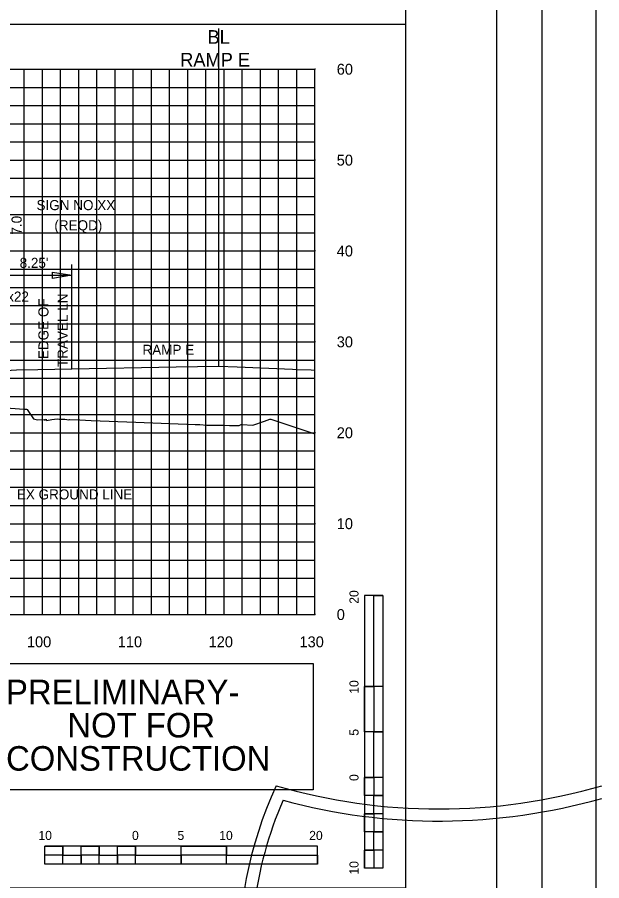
# Model space of a CAD drawing. Extents: x 1797809 to 2198143, y 249608 to 1237864.
# Drawn here: x 2195486 to 2195550.3, y 1237133.8 to 1237228.8 of the extents above; entities that cross this region are included whole.
import ezdxf

# ---------------------------------------------------------------- set-up
doc = ezdxf.new("R2010")
doc.units = 0
for name, color, linetype in [('10', 7, 'Continuous'), ('29', 7, 'Continuous'), ('3', 7, 'Continuous'), ('31', 7, 'Continuous'), ('60', 7, 'Continuous'), ('Default', 7, 'Continuous'), ('DESIGN - SHEET - Light Grid', 7, 'Continuous'), ('DESIGN - TRAFFIC CONTROL PERMANENT - Signs', 7, 'Continuous'), ('GSCOLORFILL', 7, 'Continuous'), ('GSDIMS', 7, 'Continuous'), ('GSOUTLINE', 7, 'Continuous'), ('GSSHT', 7, 'Continuous'), ('Level 30', 7, 'Continuous'), ('Level 45', 7, 'Continuous'), ('Level 55', 7, 'Continuous'), ('Level 61', 7, 'Continuous')]:
    doc.layers.add(name, color=color, linetype=linetype)

msp = doc.modelspace()

# ---------------------------------------------------------------- linework, layer by layer
at = {"layer": '29'}
for p, q in [((2195524.255, 1237165.195), (2195524.255, 1237135.195)), ((2195526.255, 1237165.195), (2195524.255, 1237165.195)), ((2195526.255, 1237165.195), (2195526.255, 1237155.195)), ((2195526.255, 1237165.195), (2195526.255, 1237135.195)), ((2195525.255, 1237155.195), (2195524.255, 1237155.195)), ((2195526.255, 1237155.195), (2195524.255, 1237155.195)), ((2195525.255, 1237155.195), (2195525.255, 1237150.195)), ((2195526.255, 1237150.195), (2195524.255, 1237150.195)), ((2195526.255, 1237150.195), (2195525.255, 1237150.195)), ((2195526.255, 1237150.195), (2195526.255, 1237145.195)), ((2195525.255, 1237145.195), (2195524.255, 1237145.195)), ((2195526.255, 1237145.195), (2195524.255, 1237145.195)), ((2195525.255, 1237145.195), (2195525.255, 1237143.195)), ((2195526.255, 1237143.195), (2195525.255, 1237143.195)), ((2195526.255, 1237143.195), (2195526.255, 1237141.195)), ((2195525.255, 1237141.195), (2195524.255, 1237141.195)), ((2195525.255, 1237141.195), (2195525.255, 1237139.195)), ((2195526.255, 1237139.195), (2195525.255, 1237139.195)), ((2195526.255, 1237139.195), (2195526.255, 1237137.195)), ((2195519.051, 1237137.63), (2195489.051, 1237137.63)), ((2195489.051, 1237135.63), (2195489.051, 1237137.63)), ((2195491.051, 1237136.63), (2195491.051, 1237137.63)), ((2195495.051, 1237136.63), (2195495.051, 1237137.63)), ((2195499.051, 1237136.63), (2195499.051, 1237137.63)), ((2195499.051, 1237135.63), (2195499.051, 1237137.63)), ((2195504.051, 1237135.63), (2195504.051, 1237137.63)), ((2195509.051, 1237136.63), (2195509.051, 1237137.63)), ((2195509.051, 1237135.63), (2195509.051, 1237137.63)), ((2195519.051, 1237135.63), (2195519.051, 1237137.63)), ((2195491.051, 1237136.63), (2195489.051, 1237136.63)), ((2195493.051, 1237135.63), (2195493.051, 1237136.63)), ((2195495.051, 1237136.63), (2195493.051, 1237136.63)), ((2195497.051, 1237135.63), (2195497.051, 1237136.63)), ((2195499.051, 1237136.63), (2195497.051, 1237136.63)), ((2195504.051, 1237135.63), (2195504.051, 1237136.63)), ((2195509.051, 1237136.63), (2195504.051, 1237136.63)), ((2195525.255, 1237137.195), (2195524.255, 1237137.195)), ((2195525.255, 1237137.195), (2195525.255, 1237135.195)), ((2195519.051, 1237135.63), (2195489.051, 1237135.63)), ((2195493.051, 1237135.63), (2195491.051, 1237135.63)), ((2195497.051, 1237135.63), (2195495.051, 1237135.63)), ((2195504.051, 1237135.63), (2195499.051, 1237135.63)), ((2195519.051, 1237135.63), (2195509.051, 1237135.63)), ((2195526.255, 1237135.195), (2195524.255, 1237135.195))]:
    msp.add_line(p, q, dxfattribs=at)
for points in [[(2195525.255, 1237155.195), (2195525.255, 1237165.195), (2195526.255, 1237165.195), (2195526.255, 1237155.195)], [(2195524.255, 1237150.195), (2195524.255, 1237155.195), (2195525.255, 1237155.195), (2195525.255, 1237150.195)], [(2195525.255, 1237145.195), (2195525.255, 1237150.195), (2195526.255, 1237150.195), (2195526.255, 1237145.195)], [(2195524.255, 1237143.195), (2195524.255, 1237145.195), (2195525.255, 1237145.195), (2195525.255, 1237143.195)], [(2195525.255, 1237141.195), (2195525.255, 1237143.195), (2195526.255, 1237143.195), (2195526.255, 1237141.195)], [(2195524.255, 1237139.195), (2195524.255, 1237141.195), (2195525.255, 1237141.195), (2195525.255, 1237139.195)], [(2195525.255, 1237137.195), (2195525.255, 1237139.195), (2195526.255, 1237139.195), (2195526.255, 1237137.195)], [(2195489.051, 1237137.63), (2195491.051, 1237137.63), (2195491.051, 1237136.63), (2195489.051, 1237136.63)], [(2195493.051, 1237137.63), (2195495.051, 1237137.63), (2195495.051, 1237136.63), (2195493.051, 1237136.63)], [(2195497.051, 1237137.63), (2195499.051, 1237137.63), (2195499.051, 1237136.63), (2195497.051, 1237136.63)], [(2195504.051, 1237137.63), (2195509.051, 1237137.63), (2195509.051, 1237136.63), (2195504.051, 1237136.63)], [(2195491.051, 1237136.63), (2195493.051, 1237136.63), (2195493.051, 1237135.63), (2195491.051, 1237135.63)], [(2195495.051, 1237136.63), (2195497.051, 1237136.63), (2195497.051, 1237135.63), (2195495.051, 1237135.63)], [(2195499.051, 1237136.63), (2195504.051, 1237136.63), (2195504.051, 1237135.63), (2195499.051, 1237135.63)], [(2195509.051, 1237136.63), (2195519.051, 1237136.63), (2195519.051, 1237135.63), (2195509.051, 1237135.63)], [(2195524.255, 1237135.195), (2195524.255, 1237137.195), (2195525.255, 1237137.195), (2195525.255, 1237135.195)]]:
    msp.add_lwpolyline(points, close=True, dxfattribs=at)
at = {"layer": '3'}
for p, q in [((2195228.783, 1237228.046), (2195528.783, 1237228.046)), ((2195492.021, 1237190.154), (2195492.021, 1237201.603))]:
    msp.add_line(p, q, dxfattribs=at)
at = {"layer": '60'}
for p, q in [((2195518.783, 1237163.106), (2195518.783, 1237223.106)), ((2195518.843, 1237223.106), (2195518.783, 1237223.106)), ((2195518.843, 1237213.106), (2195518.783, 1237213.106)), ((2195518.843, 1237203.106), (2195518.783, 1237203.106)), ((2195518.843, 1237193.106), (2195518.783, 1237193.106)), ((2195518.843, 1237183.106), (2195518.783, 1237183.106)), ((2195518.843, 1237173.106), (2195518.783, 1237173.106)), ((2195388.783, 1237163.106), (2195518.783, 1237163.106)), ((2195488.783, 1237163.046), (2195488.783, 1237163.106)), ((2195498.783, 1237163.046), (2195498.783, 1237163.106)), ((2195508.783, 1237163.046), (2195508.783, 1237163.106)), ((2195518.783, 1237163.046), (2195518.783, 1237163.106)), ((2195518.843, 1237163.106), (2195518.783, 1237163.106))]:
    msp.add_line(p, q, dxfattribs=at)
at = {"layer": 'Default'}
msp.add_line((2195508.224, 1237190.451), (2195508.224, 1237227.601), dxfattribs=at)
at = {"layer": 'DESIGN - SHEET - Light Grid'}
msp.add_lwpolyline([(2195483.25, 1237185.955), (2195486.794, 1237185.716), (2195487.022, 1237185.716), (2195487.127, 1237185.667), (2195487.816, 1237184.637), (2195488.249, 1237184.54), (2195488.993, 1237184.56), (2195489.105, 1237184.482), (2195489.214, 1237184.586), (2195489.253, 1237184.475), (2195489.812, 1237184.57), (2195490.429, 1237184.627), (2195490.65, 1237184.619), (2195491.256, 1237184.589), (2195491.701, 1237184.54), (2195491.789, 1237184.552), (2195492.9, 1237184.534), (2195493.547, 1237184.495), (2195494.166, 1237184.452), (2195499.076, 1237184.268), (2195505.615, 1237184.028), (2195506.116, 1237184.006), (2195506.881, 1237183.96), (2195507.887, 1237183.936), (2195508.065, 1237183.951), (2195508.807, 1237183.927), (2195509.369, 1237183.908), (2195510.32, 1237183.918), (2195510.399, 1237183.919), (2195510.432, 1237183.916), (2195510.671, 1237184.003), (2195510.734, 1237183.999), (2195511.936, 1237183.926), (2195513.22, 1237184.387), (2195513.811, 1237184.596), (2195513.922, 1237184.596), (2195518.783, 1237182.995)], dxfattribs=at)
at = {"layer": 'DESIGN - TRAFFIC CONTROL PERMANENT - Signs'}
msp.add_lwpolyline([(2195482.204, 1237190.443), (2195483.416, 1237190.391), (2195483.611, 1237190.39), (2195483.75, 1237190.39), (2195483.849, 1237190.097), (2195483.919, 1237189.889), (2195484.749, 1237189.952), (2195485.945, 1237190.042), (2195488.297, 1237190.085), (2195492.021, 1237190.154), (2195503.505, 1237190.365), (2195508.224, 1237190.451), (2195510.238, 1237190.365), (2195516.325, 1237190.104), (2195516.746, 1237190.086), (2195518.35, 1237190.017), (2195518.783, 1237189.999)], dxfattribs=at)
at = {"layer": 'GSCOLORFILL'}
msp.add_lwpolyline([(2195216.286, 1237123.036), (2195538.786, 1237123.036), (2195538.786, 1237333.036), (2195216.286, 1237333.036)], close=True, dxfattribs=at)
at = {"layer": 'GSDIMS'}
msp.add_lwpolyline([(2195492.021, 1237200.432), (2195489.892, 1237200.085), (2195489.892, 1237200.78)], close=True, dxfattribs=at)
at = {"layer": 'GSOUTLINE'}
for centre, major_axis, start_param, end_param in [((2195555.679, 1237125.301), (45.319, 0), 2.709569, 4.594469), ((2195532.435, 1237205.685), (63.98, 0), 4.428637, 4.996141), ((2195555.679, 1237125.301), (43.986, 0), 2.735396, 3.01287), ((2195532.435, 1237205.685), (65.313, 0), 4.446475, 4.990194)]:
    msp.add_ellipse(centre, major_axis=major_axis, ratio=0.999829, start_param=start_param, end_param=end_param, dxfattribs=at)
at = {"layer": 'GSSHT'}
for p, q in [((2195388.783, 1237223.106), (2195518.783, 1237223.106)), ((2195486.783, 1237163.106), (2195486.783, 1237223.106)), ((2195488.783, 1237163.106), (2195488.783, 1237223.106)), ((2195490.783, 1237163.106), (2195490.783, 1237223.106)), ((2195492.783, 1237163.106), (2195492.783, 1237223.106)), ((2195494.783, 1237163.106), (2195494.783, 1237223.106)), ((2195496.783, 1237163.106), (2195496.783, 1237223.106)), ((2195498.783, 1237163.106), (2195498.783, 1237223.106)), ((2195500.783, 1237163.106), (2195500.783, 1237223.106)), ((2195502.783, 1237163.106), (2195502.783, 1237223.106)), ((2195504.783, 1237163.106), (2195504.783, 1237223.106)), ((2195506.783, 1237163.106), (2195506.783, 1237223.106)), ((2195508.783, 1237163.106), (2195508.783, 1237223.106)), ((2195510.783, 1237163.106), (2195510.783, 1237223.106)), ((2195512.783, 1237163.106), (2195512.783, 1237223.106)), ((2195514.783, 1237163.106), (2195514.783, 1237223.106)), ((2195516.783, 1237163.106), (2195516.783, 1237223.106)), ((2195518.783, 1237163.106), (2195518.783, 1237223.106)), ((2195388.783, 1237221.106), (2195518.783, 1237221.106)), ((2195388.783, 1237219.106), (2195518.783, 1237219.106)), ((2195388.783, 1237217.106), (2195518.783, 1237217.106)), ((2195388.783, 1237215.106), (2195518.783, 1237215.106)), ((2195388.783, 1237213.106), (2195518.783, 1237213.106)), ((2195388.783, 1237211.106), (2195518.783, 1237211.106)), ((2195388.783, 1237209.106), (2195518.783, 1237209.106)), ((2195388.783, 1237207.106), (2195518.783, 1237207.106)), ((2195388.783, 1237205.106), (2195518.783, 1237205.106)), ((2195388.783, 1237203.106), (2195518.783, 1237203.106)), ((2195388.783, 1237201.106), (2195518.783, 1237201.106)), ((2195388.783, 1237199.106), (2195518.783, 1237199.106)), ((2195388.783, 1237197.106), (2195518.783, 1237197.106)), ((2195388.783, 1237195.106), (2195518.783, 1237195.106)), ((2195388.783, 1237193.106), (2195518.783, 1237193.106)), ((2195388.783, 1237191.106), (2195518.783, 1237191.106)), ((2195388.783, 1237189.106), (2195518.783, 1237189.106)), ((2195388.783, 1237187.106), (2195518.783, 1237187.106)), ((2195388.783, 1237185.106), (2195518.783, 1237185.106)), ((2195388.783, 1237183.106), (2195518.783, 1237183.106)), ((2195388.783, 1237181.106), (2195518.783, 1237181.106)), ((2195388.783, 1237179.106), (2195518.783, 1237179.106)), ((2195388.783, 1237177.106), (2195518.783, 1237177.106)), ((2195388.783, 1237175.106), (2195518.783, 1237175.106)), ((2195388.783, 1237173.106), (2195518.783, 1237173.106)), ((2195388.783, 1237171.106), (2195518.783, 1237171.106)), ((2195388.783, 1237169.106), (2195518.783, 1237169.106)), ((2195388.783, 1237167.106), (2195518.783, 1237167.106)), ((2195388.783, 1237165.106), (2195518.783, 1237165.106)), ((2195388.783, 1237163.106), (2195518.783, 1237163.106))]:
    msp.add_line(p, q, dxfattribs=at)
for points in [[(2195203.786, 1237118.036), (2195543.786, 1237118.036), (2195543.786, 1237338.036), (2195203.786, 1237338.036)], [(2195549.71, 1237118.036), (2195889.71, 1237118.036), (2195889.71, 1237338.036), (2195549.71, 1237338.036)]]:
    msp.add_lwpolyline(points, close=True, dxfattribs=at)
at = {"layer": 'Level 30'}
msp.add_lwpolyline([(2195483.109, 1237157.719), (2195518.572, 1237157.719), (2195518.572, 1237143.824), (2195483.109, 1237143.824)], close=True, dxfattribs=at)
at = {"layer": 'Level 45'}
msp.add_lwpolyline([(2195228.783, 1237133.046), (2195528.783, 1237133.046), (2195528.783, 1237323.046), (2195228.783, 1237323.046)], close=True, dxfattribs=at)
at = {"layer": 'Level 61'}
msp.add_line((2195483.723, 1237200.432), (2195492.021, 1237200.432), dxfattribs=at)

# ---------------------------------------------------------------- texts
at = {"layer": '10'}
for s, p in [('100', (2195487.083, 1237159.506)), ('110', (2195497.083, 1237159.506)), ('120', (2195507.083, 1237159.506)), ('130', (2195517.083, 1237159.506))]:
    msp.add_text(s, height=1.2, dxfattribs=at).set_placement(p)
at = {"layer": '29'}
for s, height, rotation, p in [('20', 0.9991, 90.0572, (2195523.581, 1237164.295)), ('10', 0.9991, 90.0572, (2195523.581, 1237154.395)), ('5', 1, 90.0572, (2195523.581, 1237149.78)), ('0', 1, 90.0572, (2195523.581, 1237144.795)), ('10', 0.9991, 0.0572, (2195488.351, 1237138.305)), ('0', 1, 0.0572, (2195498.651, 1237138.304)), ('5', 0.999, 0.0572, (2195503.652, 1237138.304)), ('10', 0.9991, 0.0572, (2195508.251, 1237138.305)), ('20', 0.9991, 0.0572, (2195518.152, 1237138.305)), ('10', 0.9991, 90.0572, (2195523.581, 1237134.495))]:
    msp.add_text(s, height=height, rotation=rotation, dxfattribs=at).set_placement(p)
at = {"layer": '31'}
for s, p in [('60', (2195521.183, 1237222.506)), ('50', (2195521.183, 1237212.506)), ('40', (2195521.183, 1237202.506)), ('30', (2195521.183, 1237192.506)), ('20', (2195521.183, 1237182.506)), ('10', (2195521.183, 1237172.506)), ('0', (2195521.183, 1237162.506))]:
    msp.add_text(s, height=1.2, dxfattribs=at).set_placement(p)
at = {"layer": '60'}
for s, p in [('BL', (2195506.96, 1237225.903)), ('RAMP E', (2195503.954, 1237223.403))]:
    msp.add_text(s, height=1.5, dxfattribs=at).set_placement(p)
at = {"layer": 'Level 30'}
for s, p in [('PRELIMINARY-', (2195484.786, 1237153.237)), ('NOT FOR', (2195491.541, 1237149.584)), ('CONSTRUCTION', (2195484.791, 1237145.931))]:
    msp.add_text(s, height=2.7, dxfattribs=at).set_placement(p)
at = {"layer": 'Level 55'}
for s, height, p in [('SIGN NO.XX', 1.1105, (2195488.14, 1237207.6)), ('(REQD)', 1.1105, (2195490.103, 1237205.379)), ("8.25'", 1.1105, (2195486.284, 1237201.244)), ('W10x22', 1.1105, (2195481.859, 1237197.535)), ('RAMP E', 1.1105, (2195499.801, 1237191.682)), ('EX GROUND LINE', 1.11046, (2195485.977, 1237175.773))]:
    msp.add_text(s, height=height, dxfattribs=at).set_placement(p)
for s, p in [("7.0'", (2195486.505, 1237204.912)), ('TRAVEL LN', (2195491.569, 1237190.336)), ('EDGE OF', (2195489.458, 1237191.209))]:
    msp.add_text(s, height=1.1105, rotation=90, dxfattribs=at).set_placement(p)

doc.saveas('drawing.dxf')
